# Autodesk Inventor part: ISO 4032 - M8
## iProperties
Comments: To add or edit properties for Autodesk Inventor files, use iProperties.
Created: 2004-08
Part Number: ISO 4032 - M8
Vendor: Autodesk Inc.
Document SubType Name: Modeling
Designer: John Blackburn
Material: Default
Description: Hex Nut
Standard: ISO 4032
Alert: To add or edit properties for Autodesk Inventor files, use iProperties.
Control State: 0
Master: False
Checked Out: False
Shininess: 64.0
Length Units: 11269
Angle Units: 11279
Time Units: 11290
Mass Units: 11283
Length Display Precision: 3
Angle Display Precision: 2
Compacted: True
EGR: 1
Density: 0.0
Volumn: 0.0
Area: 0.0
PropertySet Name: Model Information
Author: John Blackburn
Revision Number: 8
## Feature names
1. Body [Extrusion]
2. Chamfer1 [Revolution]
3. Thread [Hole]
4. Chamfer2
5. Chamfer3
